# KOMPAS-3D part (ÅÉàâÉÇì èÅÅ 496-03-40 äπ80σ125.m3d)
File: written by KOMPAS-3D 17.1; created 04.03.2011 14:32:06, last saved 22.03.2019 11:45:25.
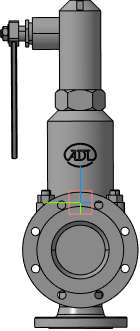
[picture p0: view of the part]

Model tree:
1. Операция без истории:1

Referenced files in C:\Users\tra\Desktop\Детали с марк. для Сферы\bsv\Desktop\Si 57\: VIC_496_80x125_3d.a3d
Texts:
  Viktor2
